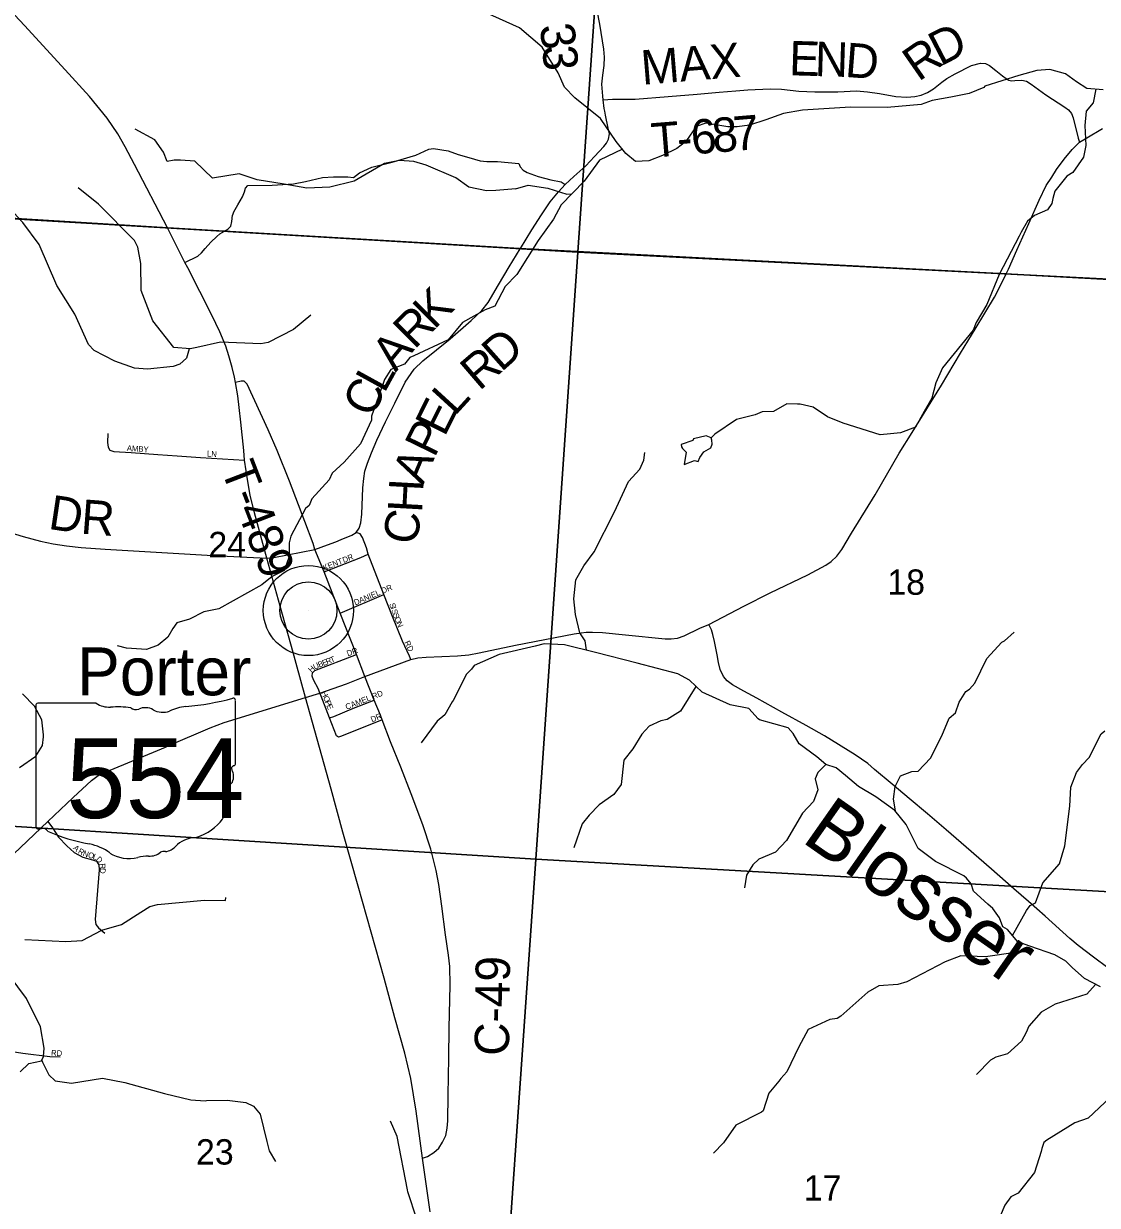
# Model space of a CAD drawing. Extents: x 1878108 to 2183446, y 146837 to 508383.
# Drawn here: x 2027893 to 2037252, y 333002 to 343304 of the extents above; entities that cross this region are included whole.
import ezdxf

# ---------------------------------------------------------------- set-up
doc = ezdxf.new("R2010")
doc.units = 0
for name, color, linetype in [('GM_X_County_Road', 7, 'Continuous'), ('GM_X_County_Road_Text', 7, 'Continuous'), ('GM_X_Minor_River', 7, 'Continuous'), ('GM_X_Minor_River_Text', 7, 'Continuous'), ('GM_X_Section', 7, 'Continuous'), ('GM_X_Section_Text', 7, 'Continuous'), ('GM_X_State_Location', 7, 'Continuous'), ('GM_X_State_Route', 7, 'Continuous'), ('GM_X_State_Shield', 7, 'Continuous'), ('GM_X_Township', 7, 'Continuous'), ('GM_X_Township_Road', 7, 'Continuous'), ('GM_X_Township_Road_Text', 7, 'Continuous'), ('GM_X_Township_ROW', 7, 'Continuous'), ('GM_X_Township_Subdivision', 7, 'Continuous'), ('GM_X_Township_Subdivision_Text', 7, 'Continuous'), ('GM_X_Unincorporated', 7, 'Continuous'), ('GM_X_Unincorporated_Location', 7, 'Continuous'), ('GM_X_Unincorporated_Text', 7, 'Continuous')]:
    doc.layers.add(name, color=color, linetype=linetype)

msp = doc.modelspace()

# ---------------------------------------------------------------- linework, layer by layer
at = {"layer": 'GM_X_County_Road'}
for points in [[(2032958, 342540), (2032953, 342566), (2032945, 342639), (2032941, 342673), (2032934, 342776), (2032941, 342856), (2032954, 342939), (2032956, 343012), (2032949, 343082), (2032915, 343300), (2032893, 343420)], [(2032221, 341341), (2032223, 341344), (2032321, 341507), (2032406, 341638), (2032483, 341750), (2032554, 341838), (2032613, 341901), (2032689, 341972), (2032792, 342064), (2032869, 342147), (2032949, 342233), (2032972, 342262), (2032991, 342296), (2032999, 342345), (2032989, 342393), (2032964, 342506), (2032958, 342540)], [(2030012, 338644), (2030073, 338649), (2030430, 338721), (2030487, 338740), (2030542, 338762), (2030614, 338788), (2030661, 338806), (2030753, 338846), (2030792, 338869), (2030816, 338905), (2030833, 338953), (2030842, 339027), (2030849, 339259), (2030857, 339338), (2030868, 339404), (2030890, 339474), (2030924, 339562), (2030971, 339674), (2031047, 339834), (2031127, 339996), (2031218, 340179), (2031296, 340292), (2031372, 340364), (2031610, 340558), (2031794, 340717), (2031887, 340804), (2031941, 340873), (2032033, 341027), (2032125, 341183), (2032221, 341341)], [(2026573, 339023), (2026736, 339019), (2026867, 339017), (2027032, 339010), (2027260, 338998), (2027368, 338982), (2027487, 338954), (2027890, 338833), (2028039, 338792), (2028149, 338769), (2028265, 338752), (2028395, 338738), (2028602, 338722), (2029492, 338671), (2030012, 338644)], [(2031368, 333413), (2031414, 333429), (2031468, 333462), (2031511, 333500), (2031544, 333552), (2031572, 333610), (2031584, 333676), (2031590, 333739), (2031592, 333962), (2031598, 334289), (2031603, 334546), (2031611, 334922), (2031609, 335086), (2031597, 335184), (2031570, 335362), (2031539, 335611), (2031513, 335799), (2031489, 335921), (2031442, 336108), (2031372, 336319), (2031271, 336590), (2031181, 336821), (2031090, 337042), (2031019, 337235), (2031002, 337275), (2030948, 337407), (2030867, 337612), (2030795, 337805), (2030653, 338165), (2030512, 338525), (2030430, 338721)], [(2037342, 335073), (2037217, 335167), (2037085, 335269), (2037013, 335328), (2036797, 335522), (2036653, 335650), (2036524, 335763), (2036330, 335933), (2036109, 336125), (2035935, 336277), (2035772, 336415), (2035611, 336550), (2035462, 336675), (2035309, 336803), (2035250, 336854), (2035141, 336931), (2034874, 337095), (2034713, 337187), (2034502, 337301), (2034283, 337423), (2034171, 337484), (2034071, 337541), (2034025, 337574), (2033993, 337614), (2033965, 337674), (2033950, 337736), (2033937, 337802), (2033914, 337918), (2033901, 337978), (2033888, 338019), (2033865, 338066)]]:
    msp.add_lwpolyline(points, dxfattribs=at)
at = {"layer": 'GM_X_Minor_River'}
for points in [[(2037302, 342728), (2037160, 342738), (2037070, 342796), (2036974, 342868), (2036838, 342906), (2036724, 342896), (2036568, 342851), (2036272, 342758), (2036262, 342748), (2036134, 342694), (2035975, 342664), (2035813, 342635), (2035717, 342599), (2035419, 342573), (2035099, 342576), (2034681, 342549), (2034517, 342521), (2034361, 342465), (2034219, 342418), (2034111, 342406), (2034030, 342404), (2033838, 342436), (2033754, 342409), (2033670, 342287), (2033662, 342275), (2033586, 342217), (2033460, 342154), (2033342, 342108), (2033226, 342104), (2033142, 342172), (2033058, 342278), (2032922, 342478), (2032696, 342658), (2032608, 342752), (2032552, 342875), (2032412, 343099), (2032214, 343269), (2031924, 343399)], [(2029336, 340469), (2029311, 340388), (2029253, 340336), (2029195, 340314), (2028973, 340291), (2028859, 340301), (2028687, 340362), (2028508, 340456), (2028458, 340508), (2028339, 340773), (2028182, 341021), (2028027, 341380), (2027887, 341570), (2027381, 342112), (2027256, 342196), (2026886, 342324), (2026819, 342346), (2026549, 342439), (2026372, 342543), (2026268, 342673), (2026197, 342815), (2026203, 342912)], [(2037239, 342732), (2037216, 342613), (2037154, 342541), (2037142, 342415), (2037151, 342241), (2037131, 342141), (2037039, 342008), (2036985, 341976), (2036881, 341844), (2036863, 341780), (2036855, 341736), (2036816, 341680), (2036704, 341631), (2036644, 341583), (2036588, 341487), (2036570, 341451), (2036397, 341116), (2036289, 340856), (2036195, 340700), (2036169, 340633), (2035902, 340305), (2035844, 340172), (2035810, 340038), (2035743, 339922), (2035667, 339786), (2035537, 339736), (2035449, 339727), (2035359, 339721), (2035035, 339821), (2034900, 339878), (2034774, 339962), (2034662, 339986), (2034638, 339986), (2034544, 339990), (2034428, 339922), (2034330, 339921), (2034268, 339895), (2034106, 339853), (2033919, 339726), (2033887, 339694)], [(2032184, 341865), (2032010, 341849), (2031926, 341846), (2031772, 341880), (2031659, 341960), (2031401, 342070), (2031295, 342102), (2031170, 342111), (2031038, 342085), (2030774, 341932), (2030562, 341879), (2030360, 341869), (2030165, 341906), (2029929, 341942), (2029771, 341994), (2029538, 341957), (2029384, 342105), (2029260, 342115), (2029205, 342113), (2029145, 342104), (2029111, 342185), (2029035, 342291), (2028866, 342385)], [(2033113, 342209), (2032911, 342115), (2032780, 341930), (2032578, 341724), (2032512, 341600), (2032377, 341413), (2032193, 341117), (2032091, 341012), (2032000, 340840), (2031916, 340810), (2031718, 340699), (2031594, 340547), (2031293, 340408), (2031259, 340394), (2031213, 340336), (2031093, 340290), (2031037, 340202), (2031031, 340184), (2030924, 339883), (2030926, 339847), (2030828, 339641), (2030686, 339480), (2030583, 339386), (2030555, 339328), (2030405, 339163), (2030381, 339105), (2030351, 339077), (2030222, 338837), (2030206, 338779), (2030206, 338656), (2030202, 338642), (2030164, 338536), (2030060, 338486), (2029970, 338412), (2029595, 338203), (2029463, 338178), (2029339, 338112), (2029228, 338082), (2029192, 338032), (2029150, 337956), (2029066, 337887), (2028964, 337849), (2028790, 337861), (2028710, 337881)], [(2030396, 340764), (2030244, 340637), (2030024, 340526), (2029960, 340512), (2029608, 340527), (2029401, 340481), (2029343, 340468), (2029201, 340482), (2029020, 340714), (2028916, 340977), (2028913, 341213), (2028887, 341356), (2028858, 341414), (2028545, 341732), (2028369, 341874)], [(2032179, 341864), (2032290, 341896), (2032461, 341871), (2032627, 341817), (2032667, 341821)], [(2033887, 339694), (2033841, 339712), (2033731, 339686), (2033727, 339670), (2033623, 339634), (2033627, 339616), (2033637, 339600), (2033667, 339568), (2033651, 339460), (2033741, 339496), (2033773, 339486), (2033787, 339522), (2033823, 339572), (2033882, 339607)], [(2033882, 339607), (2033895, 339638), (2033891, 339674), (2033887, 339694)], [(2032798, 337841), (2032788, 337925), (2032742, 337993), (2032702, 338153), (2032688, 338289), (2032705, 338455), (2032777, 338577), (2032867, 338701), (2033044, 339048), (2033166, 339313), (2033264, 339419), (2033298, 339499), (2033306, 339567)], [(2035493, 336442), (2035475, 336542), (2035489, 336654), (2035536, 336746), (2035636, 336785), (2035690, 336787), (2035798, 336901), (2035896, 337097), (2035959, 337250), (2036015, 337296), (2036047, 337388), (2036105, 337482), (2036137, 337502), (2036185, 337556), (2036290, 337771), (2036418, 337911), (2036444, 337925), (2036526, 337998)], [(2037279, 334907), (2037139, 334981), (2037032, 335077), (2036978, 335131), (2036882, 335187), (2036662, 335263), (2036560, 335301), (2036468, 335407), (2036428, 335431), (2036398, 335509), (2036342, 335591), (2036298, 335628), (2036172, 335740), (2036152, 335804), (2036110, 335856), (2036088, 335874), (2035842, 336000), (2035690, 336112), (2035584, 336322), (2035488, 336444), (2035320, 336565), (2035170, 336655), (2035058, 336751), (2034974, 336817), (2034885, 336845), (2034806, 336913), (2034654, 337025), (2034600, 337117), (2034556, 337165), (2034306, 337235), (2034294, 337243), (2034214, 337335), (2034050, 337365), (2033806, 337477), (2033698, 337581), (2033594, 337635), (2033242, 337730), (2032876, 337822), (2032608, 337888), (2032430, 337899), (2032352, 337877), (2032038, 337806), (2031820, 337708), (2031796, 337678), (2031754, 337632), (2031637, 337403), (2031627, 337393), (2031563, 337278), (2031497, 337222), (2031357, 337035)], [(2033753, 337527), (2033618, 337311), (2033502, 337237), (2033446, 337225), (2033346, 337181), (2033282, 337111), (2033203, 336982), (2033125, 336884), (2033101, 336672), (2033037, 336584), (2032909, 336493), (2032822, 336405), (2032762, 336329), (2032688, 336120)], [(2027856, 336820), (2028000, 336918), (2028058, 337011), (2028066, 337087), (2028066, 337103), (2028052, 337235), (2027986, 337353), (2027884, 337461)], [(2036513, 335356), (2036635, 335573), (2036666, 335615), (2036712, 335639), (2036776, 335814), (2036922, 335980), (2036968, 336138), (2037013, 336481), (2037021, 336649), (2037071, 336777), (2037123, 336845), (2037180, 336906), (2037286, 337114), (2037316, 337140)], [(2034885, 336845), (2034815, 336777), (2034793, 336721), (2034815, 336625), (2034777, 336523), (2034682, 336420), (2034542, 336184), (2034446, 336082), (2034302, 336019), (2034249, 335971), (2034193, 335881), (2034177, 335771)], [(2027902, 335320), (2028260, 335303), (2028404, 335311), (2028575, 335400), (2028747, 335450), (2028913, 335559), (2028993, 335607), (2029060, 335625), (2029470, 335662), (2029652, 335660), (2029655, 335687)], [(2036592, 335289), (2036537, 335206), (2036277, 335170), (2036062, 335177), (2035924, 335125), (2035590, 334952), (2035512, 334928), (2035347, 334916), (2035251, 334860), (2035017, 334651), (2034985, 334631), (2034919, 334623), (2034732, 334536), (2034650, 334384), (2034544, 334167), (2034494, 334107), (2034476, 334085), (2034389, 333981), (2034339, 333827), (2034323, 333815), (2034101, 333700), (2033994, 333548), (2033906, 333458)], [(2027861, 334165), (2027939, 334239), (2028047, 334261), (2028067, 334301), (2028073, 334373), (2028039, 334560), (2027919, 334806), (2027767, 335010)], [(2037236, 334929), (2037161, 334843), (2036885, 334756), (2036763, 334686), (2036656, 334564), (2036630, 334508), (2036590, 334434), (2036468, 334323), (2036368, 334295), (2036320, 334269), (2036199, 334144)], [(2037847, 334758), (2037838, 334558), (2037785, 334398), (2037647, 334207), (2037617, 334135), (2037617, 334051), (2037463, 333997), (2037366, 333946), (2037172, 333762), (2037056, 333721), (2036811, 333571), (2036785, 333549), (2036769, 333497), (2036763, 333471), (2036705, 333288), (2036561, 333110), (2036497, 333076), (2036446, 333003), (2036406, 332909), (2036222, 332817), (2036138, 332779), (2036036, 332780), (2035878, 332756)], [(2028060, 334263), (2028053, 334257), (2028113, 334139), (2028167, 334089), (2028311, 334068), (2028579, 334110), (2028775, 334072), (2029120, 333977), (2029350, 333923), (2029474, 333914), (2029488, 333916), (2029666, 333918), (2029830, 333898), (2029896, 333866), (2029954, 333796), (2030012, 333558), (2030034, 333478), (2030088, 333386)], [(2031319, 332882), (2031243, 333120), (2031239, 333138), (2031149, 333602), (2031090, 333736)]]:
    msp.add_lwpolyline(points, dxfattribs=at)
at = {"layer": 'GM_X_Section'}
for points in [[(2027883, 347107), (2033105, 346799), (2032724, 341311), (2027503, 341621)], [(2033105, 346799), (2038385, 346465), (2038042, 341041), (2032724, 341311)], [(2027503, 341621), (2032724, 341311), (2032358, 336020), (2027176, 336347)], [(2032724, 341311), (2038042, 341041), (2037721, 335715), (2032358, 336020)], [(2032358, 336020), (2031987, 330736), (2026777, 331044), (2026745, 331046), (2027176, 336347)], [(2037721, 335715), (2037378, 330411), (2031987, 330736), (2032358, 336020)]]:
    msp.add_lwpolyline(points, close=True, dxfattribs=at)
at = {"layer": 'GM_X_State_Route'}
for points in [[(2029323, 341175), (2029299, 341221), (2029263, 341292), (2029147, 341524), (2028858, 342076), (2028777, 342231), (2028714, 342344), (2028621, 342479), (2028468, 342668), (2028256, 342903), (2027900, 343287), (2027689, 343519)], [(2030349, 337431), (2030474, 337467), (2030708, 337548), (2030867, 337612), (2031269, 337761), (2031330, 337776), (2031402, 337782), (2031675, 337793), (2031774, 337803), (2031863, 337819), (2032179, 337886), (2032692, 337985), (2032753, 337994), (2032797, 337998), (2032850, 337999), (2032937, 337995), (2033138, 337975), (2033486, 337940), (2033537, 337940), (2033592, 337948), (2033651, 337968), (2033788, 338035), (2033865, 338066), (2034171, 338227), (2034400, 338342), (2034729, 338499), (2034884, 338582), (2034931, 338615), (2034980, 338663), (2035025, 338720), (2035110, 338862), (2035315, 339196), (2035523, 339560), (2035639, 339739), (2035893, 340153), (2036058, 340432), (2036186, 340642), (2036354, 340920), (2036434, 341073), (2036458, 341123), (2036476, 341163), (2036551, 341330), (2036654, 341562), (2036745, 341766), (2036807, 341894), (2036854, 341967), (2036897, 342033), (2036964, 342124), (2037032, 342206), (2037095, 342271), (2037160, 342309), (2037297, 342390)], [(2031435, 332946), (2031368, 333413), (2031314, 333824), (2031267, 334108), (2031215, 334330), (2031129, 334636), (2031035, 334982), (2030808, 335785), (2030676, 336257), (2030573, 336631), (2030349, 337431), (2030227, 337874), (2030196, 337988), (2030129, 338227), (2030012, 338644), (2029904, 339040), (2029868, 339193), (2029846, 339313), (2029819, 339499), (2029811, 339583), (2029787, 339829), (2029770, 339957), (2029759, 340061), (2029739, 340177), (2029731, 340221), (2029711, 340307), (2029681, 340407), (2029654, 340494), (2029603, 340618), (2029533, 340763), (2029323, 341175)], [(2029159, 337010), (2029518, 337164), (2029642, 337213), (2030349, 337431)], [(2027109, 335425), (2027129, 335444), (2027212, 335510), (2027326, 335611), (2028103, 336348), (2028324, 336559), (2028484, 336706), (2028543, 336751), (2028612, 336783), (2029129, 336997), (2029159, 337010)]]:
    msp.add_lwpolyline(points, dxfattribs=at)
at = {"layer": 'GM_X_State_Shield'}
for p, q in [((2029738, 336853), (2029738, 337405)), ((2027998, 337361), (2027998, 336304)), ((2028525, 337379), (2028015, 337379)), ((2029738, 336853), (2029738, 336853))]:
    msp.add_line(p, q, dxfattribs=at)
for centre, major_axis, start_param, end_param in [((2029118, 338820), (1845, 0), 4.814394, 5.042369), ((2029719, 337408), (19.4, 0), 6.141152, 7.989035), ((2028018, 337363), (20.2, 0), 1.712693, 3.28349), ((2028646, 337502), (196, 0), 4.042523, 4.731795), ((2028711, 336786), (702, 0), 1.404758, 1.657858), ((2028870, 337369), (56.4, 0), 3.836095, 5.185415), ((2028953, 337247), (117, 0), 0.950623, 2.079405), ((2029105, 337414), (141, 0), 4.081561, 5.145723), ((2029354, 337057), (371, 0), 1.699011, 2.107814), ((2029734, 336812), (30, 0), 1.883978, 3.671073), ((2029543, 336742), (180, 0), 5.934695, 6.695948), ((2029718, 336851), (20.7, 0), 5.05454, 6.418171), ((2029808, 336621), (131, 0), 2.387724, 3.262537), ((2029222, 336551), (462, 0), 5.101752, 6.440018), ((2028018, 336302), (20.3, 0), 3.00124, 4.508301), ((2028021, 336410), (155, 0), 4.665946, 4.897461), ((2028053, 336244), (56, 0), 0.519207, 1.627899), ((2028760, 337193), (1333, 0), 4.195997, 4.488961), ((2029416, 336008), (253, 0), 1.647645, 2.488434), ((2028362, 335830), (417, 0), 0.823519, 1.323587), ((2028813, 336238), (265, 0), 4.026481, 4.996735), ((2028985, 336159), (141, 0), 4.691044, 5.507374), ((2029113, 336057), (39.7, 0), 1.147584, 2.315152), ((2029096, 336202), (149, 0), 4.937069, 5.64225), ((2028966, 335873), (217, 0), 1.495662, 1.94098)]:
    msp.add_ellipse(centre, major_axis=major_axis, ratio=0.8, start_param=start_param, end_param=end_param, dxfattribs=at)
at = {"layer": 'GM_X_Township'}
for points in [[(2049375, 348847), (2049004, 342247), (2048900, 340387), (2047784, 340461), (2043752, 340720), (2039375, 340963), (2036450, 341124), (2032214, 341344), (2029149, 341524), (2023521, 341871), (2022085, 341976), (2018358, 342153)], [(2018358, 342153), (2022085, 341976), (2023521, 341871), (2029149, 341524), (2032214, 341344), (2036450, 341124), (2039375, 340963), (2043752, 340720), (2047784, 340461)]]:
    msp.add_lwpolyline(points, dxfattribs=at)
at = {"layer": 'GM_X_Township_Road'}
for points in [[(2032945, 342639), (2033027, 342645), (2033223, 342647), (2033511, 342669), (2033763, 342691), (2033955, 342708), (2034101, 342720), (2034205, 342727), (2034400, 342736), (2034500, 342734), (2034651, 342715), (2034789, 342710), (2034991, 342709), (2035152, 342719), (2035249, 342711), (2035352, 342695), (2035496, 342670), (2035592, 342664), (2035662, 342670), (2035716, 342681), (2035772, 342703), (2035824, 342735), (2035895, 342795), (2035941, 342827), (2036012, 342868), (2036156, 342939), (2036234, 342960), (2036277, 342956), (2036312, 342939), (2036367, 342896), (2036426, 342849), (2036456, 342827), (2036479, 342812), (2036503, 342806), (2036533, 342809), (2036594, 342812), (2036635, 342802), (2036675, 342778), (2036802, 342685), (2036968, 342577), (2037000, 342552), (2037027, 342521), (2037042, 342484), (2037085, 342305), (2037095, 342271)], [(2029299, 341221), (2029410, 341277), (2029442, 341306), (2029475, 341344), (2029524, 341399), (2029576, 341448), (2029603, 341471), (2029643, 341495), (2029672, 341513), (2029699, 341539), (2029708, 341579), (2029713, 341635), (2029715, 341638)], [(2030430, 338721), (2030416, 338773), (2030343, 338964), (2030210, 339315), (2030102, 339583), (2030024, 339763), (2029840, 340162), (2029814, 340187), (2029789, 340188), (2029739, 340177)]]:
    msp.add_lwpolyline(points, dxfattribs=at)
at = {"layer": 'GM_X_Township_ROW'}
msp.add_lwpolyline([(2029715, 341638), (2029724, 341664), (2029759, 341725), (2029800, 341795), (2029819, 341839), (2029828, 341869), (2029847, 341892), (2030060, 341896), (2030244, 341907), (2030349, 341929), (2030499, 341964), (2030595, 341968), (2030720, 341968), (2030768, 341964), (2030820, 342005), (2030929, 342053), (2031106, 342096), (2031310, 342159), (2031424, 342209), (2031464, 342215), (2031593, 342197), (2031679, 342164), (2031774, 342137), (2031871, 342109), (2031930, 342103), (2032024, 342103), (2032208, 342085), (2032221, 342056), (2032246, 342028), (2032281, 342006), (2032378, 341973), (2032487, 341943), (2032578, 341924), (2032613, 341901)], dxfattribs=at)
at = {"layer": 'GM_X_Township_Subdivision'}
for points in [[(2028627, 339730), (2028624, 339652), (2028630, 339612), (2028645, 339587), (2028678, 339575), (2028830, 339566), (2029063, 339548), (2029231, 339536)], [(2029231, 339536), (2029434, 339521), (2029819, 339499)], [(2031269, 337761), (2031257, 337789), (2031195, 337922), (2031107, 338137), (2031033, 338328), (2030897, 338680), (2030882, 338734), (2030846, 338826), (2030825, 338857), (2030792, 338869)], [(2030512, 338525), (2030833, 338650), (2030897, 338680)], [(2030653, 338165), (2031033, 338328)], [(2030474, 337467), (2030462, 337502), (2030418, 337583), (2030409, 337617), (2030410, 337644), (2030431, 337664), (2030795, 337805)], [(2031019, 337235), (2030662, 337092), (2030638, 337085), (2030620, 337097), (2030560, 337253), (2030487, 337441), (2030474, 337467)], [(2030560, 337253), (2030596, 337263), (2030768, 337336), (2030948, 337407)], [(2028103, 336348), (2028143, 336293), (2028197, 336211), (2028270, 336137), (2028332, 336079), (2028408, 336037), (2028492, 336016), (2028527, 336002), (2028549, 335970), (2028550, 335926), (2028517, 335493), (2028522, 335452), (2028544, 335422), (2028599, 335374)], [(2027431, 334396), (2027533, 334384), (2027885, 334330), (2028121, 334300), (2028210, 334296)]]:
    msp.add_lwpolyline(points, dxfattribs=at)
at = {"layer": 'GM_X_Unincorporated'}
for radius in [393, 249]:
    msp.add_circle((2030375, 338188), radius, dxfattribs=at)
at = {"layer": 'GM_X_Unincorporated_Location'}
msp.add_line((2030375, 338188), (2030375, 338188), dxfattribs=at)

# ---------------------------------------------------------------- texts
at = {"layer": 'GM_X_County_Road_Text'}
for s, rotation, p in [('3', 279.0611, (2032387, 343284)), ('3', 273.7442, (2032415, 343109)), ('K', 44.96, (2031471, 340631)), ('R', 45.163, (2031299, 340458)), ('D', 41.5276, (2032055, 340261)), ('A', 50.5526, (2031135, 340259)), ('R', 40.6407, (2031864, 340097)), ('C', 63.8839, (2030930, 339859)), ('L', 61.2028, (2031036, 340075)), ('L', 47.5888, (2031650, 339878)), ('E', 63.5634, (2031562, 339695)), ('P', 64.0257, (2031474, 339513)), ('A', 67.2319, (2031374, 339274)), ('H', 86.8531, (2031365, 339037)), ('D', 351.475, (2028100, 338901)), ('R', 355.575, (2028385, 338859)), ('C', 78.5584, (2031310, 338748)), ('C-49', 89.3108, (2032123, 334305))]:
    msp.add_text(s, height=300, rotation=rotation, dxfattribs=at).set_placement(p)
at = {"layer": 'GM_X_Minor_River_Text'}
msp.add_text('Blosser', height=500, rotation=325.0018, dxfattribs=at).set_placement((2034662, 336180))
at = {"layer": 'GM_X_Section_Text'}
for s, p in [('24', (2029503, 338653)), ('18', (2035421, 338325)), ('23', (2029395, 333358)), ('17', (2034693, 333044))]:
    msp.add_text(s, height=221, rotation=0, dxfattribs=at).set_placement(p)
at = {"layer": 'GM_X_State_Location'}
msp.add_text('554', height=1, rotation=0, dxfattribs=at).set_placement((2028496, 336690))
for s in ['s', 'r']:
    msp.add_text(s, height=1, dxfattribs=at).set_placement((2028849, 336763))
at = {"layer": 'GM_X_State_Shield'}
msp.add_text('554', height=696.1, dxfattribs=at).set_placement((2028264, 336379))
at = {"layer": 'GM_X_Township_Road_Text'}
for s, rotation, p in [('D', 27.4269, (2035885, 342929)), ('MAX', 4.7138, (2033286, 342771)), ('E', 358.2983, (2034562, 342855)), ('N', 358.2621, (2034786, 342848)), ('D', 355.5585, (2035047, 342841)), ('R', 34.7672, (2035692, 342794)), ('T', 4.5949, (2033375, 342136)), ('6', 4.6033, (2033721, 342164)), ('8', 4.6475, (2033906, 342179)), ('7', 4.7929, (2034091, 342194)), ('-', 4.5949, (2033598, 342154)), ('T-489', 291.0553, (2029609, 339423))]:
    msp.add_text(s, height=300, rotation=rotation, dxfattribs=at).set_placement(p)
at = {"layer": 'GM_X_Township_Subdivision_Text'}
for s, rotation, p in [('AMBY', 355.9114, (2028791, 339580)), ('LN', 356.989, (2029490, 339531)), ('KENT', 20.9194, (2030512, 338536)), ('DR', 21.2487, (2030683, 338602)), ('DANIEL DR', 23.0961, (2030784, 338232)), ('S', 288.5127, (2031079, 338244)), ('I', 288.4866, (2031090, 338211)), ('S', 288.4973, (2031097, 338190)), ('S', 291.1144, (2031109, 338154)), ('O', 293.4332, (2031122, 338120)), ('N', 293.5135, (2031140, 338079)), ('RD', 295.2018, (2031210, 337911)), ('DR', 19.4434, (2030719, 337788)), ('H', 43.3149, (2030401, 337644)), ('U', 25.2162, (2030430, 337671)), ('B', 21.3775, (2030469, 337690)), ('E', 21.3651, (2030506, 337704)), ('R', 21.3549, (2030538, 337717)), ('T', 21.3872, (2030575, 337731)), ('H', 294.5507, (2030484, 337472)), ('O', 291.8867, (2030502, 337432)), ('P', 291.4514, (2030518, 337392)), ('CAMEL RD', 21.5033, (2030709, 337322)), ('E', 291.4549, (2030531, 337359)), ('DR', 22.3821, (2030930, 337212)), ('A', 317.5513, (2028319, 336112)), ('R', 330.8097, (2028362, 336075)), ('N', 339.9835, (2028404, 336052)), ('O', 344.4598, (2028450, 336036)), ('L', 338.782, (2028491, 336024)), ('D', 314.9536, (2028519, 336015)), ('R', 276.7184, (2028553, 335980)), ('D', 268.2947, (2028558, 335943)), ('RD', 356.8215, (2028131, 334308))]:
    msp.add_text(s, height=50, rotation=rotation, dxfattribs=at).set_placement(p)
at = {"layer": 'GM_X_Unincorporated_Text'}
msp.add_text('Porter', height=417, rotation=0, dxfattribs=at).set_placement((2028359, 337449))

doc.saveas('drawing.dxf')
